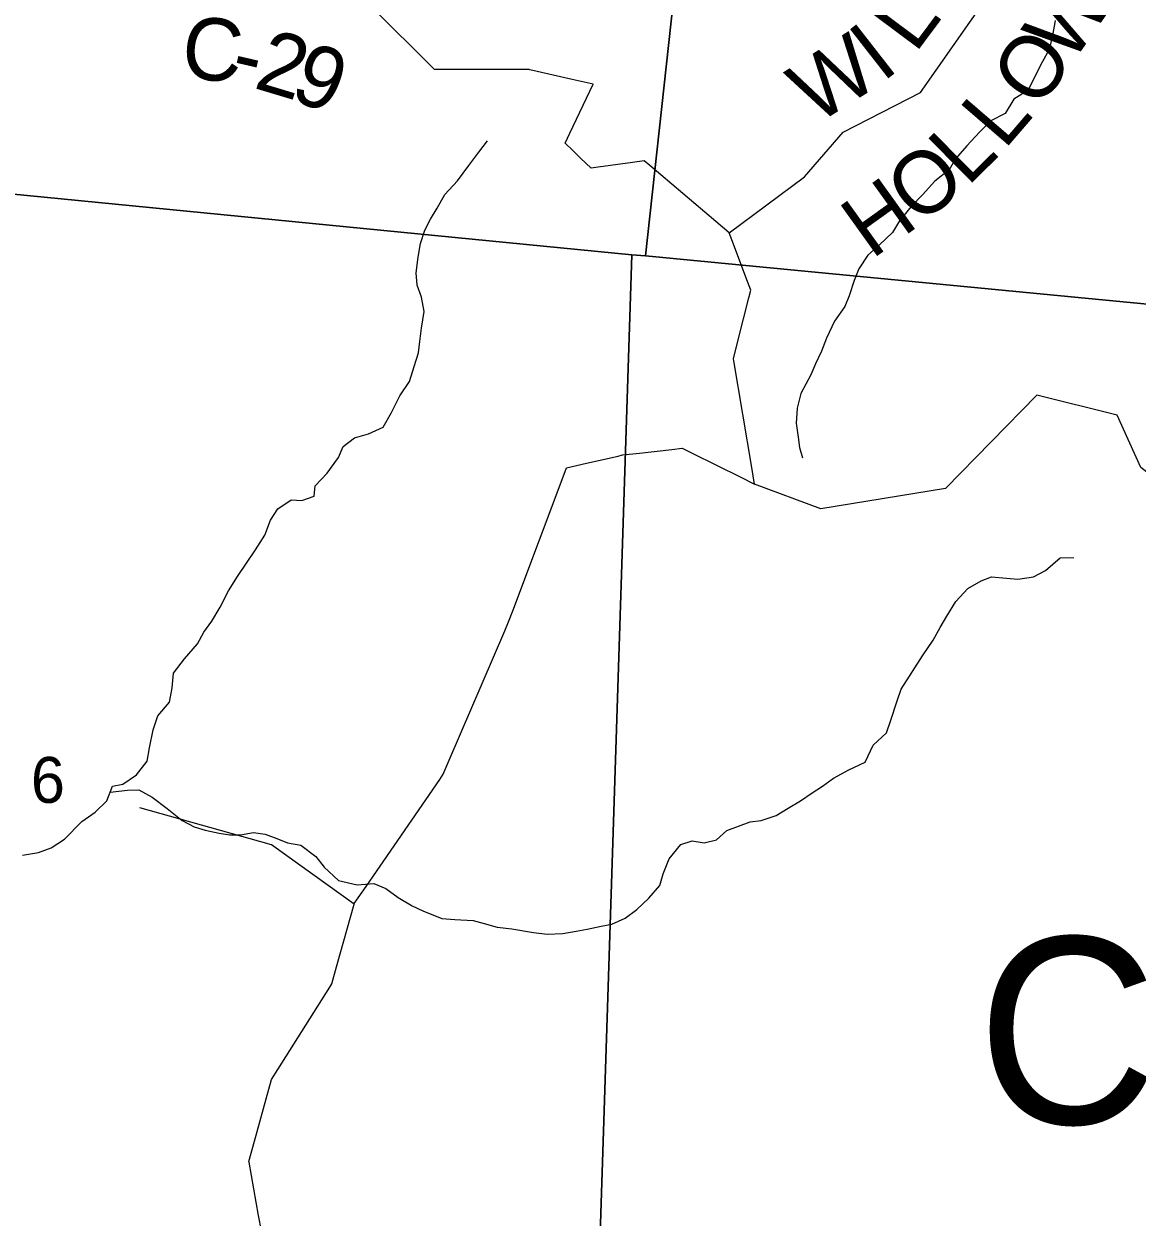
# Model space of a CAD drawing. Extents: x 1715311 to 2083412, y 146837 to 553079.
# Drawn here: x 1925685 to 1931050, y 401506 to 407256 of the extents above; entities that cross this region are included whole.
import ezdxf

# ---------------------------------------------------------------- set-up
doc = ezdxf.new("R2010")
doc.units = 0
for name, color, linetype in [('GM_X_County_Road', 7, 'Continuous'), ('GM_X_County_Road_Text', 7, 'Continuous'), ('GM_X_Minor_River', 7, 'Continuous'), ('GM_X_Section', 7, 'Continuous'), ('GM_X_Section_Text', 7, 'Continuous'), ('GM_X_Township_Road', 7, 'Continuous'), ('GM_X_Township_Road_Text', 7, 'Continuous'), ('GM_X_Township_ROW', 7, 'Continuous'), ('GM_X_Township_Text', 7, 'Continuous')]:
    doc.layers.add(name, color=color, linetype=linetype)

msp = doc.modelspace()

# ---------------------------------------------------------------- linework, layer by layer
at = {"layer": 'GM_X_County_Road'}
msp.add_lwpolyline([(1926830, 401440.6), (1926816.6, 401514.7), (1926770.3, 401771.3), (1926769.8, 401773.5), (1926796.8, 401871.9), (1926865.8, 402123.4), (1926878.1, 402168.6), (1926908.8, 402217.1), (1927159.2, 402614.2), (1927169, 402629.8), (1927192.1, 402712.4), (1927276.5, 403013.7), (1927277.3, 403016.8), (1927334.5, 403100), (1927689.4, 403615.5), (1927706.5, 403640.5), (1927735.6, 403708.4), (1928002.9, 404331.4), (1928021.4, 404374.5), (1928041.6, 404428.2), (1928298.5, 405111.6), (1928300.2, 405116.5), (1928396.7, 405138.7), (1928549.2, 405173.7), (1928571, 405178.7), (1928652.3, 405187.8), (1928807.8, 405205.2), (1928857.9, 405210.8), (1928906.2, 405186.9), (1929139.9, 405071.4), (1929206.8, 405038.3), (1929193.2, 405118.9), (1929106, 405633.1), (1929104.5, 405641.9), (1929128, 405734.3), (1929179.5, 405936.4), (1929188.8, 405972.8), (1929165.2, 406035.2), (1929110.1, 406181.6), (1929084.5, 406249.6), (1929020.5, 406303.8), (1928702.4, 406573.6), (1928675.3, 406596.6), (1928607.2, 406587), (1928452.3, 406565.2), (1928418.6, 406560.5), (1928368.1, 406609.3), (1928330.6, 406645.5), (1928294.2, 406680.8), (1928317.1, 406729.3), (1928428.4, 406965.1), (1928428.6, 406965.6), (1928327.5, 406988.6), (1928124.1, 407034.8), (1928119.7, 407035.8), (1927664.4, 407035.8), (1927620.7, 407079.1), (1927398.7, 407299.6)], dxfattribs=at)
at = {"layer": 'GM_X_Minor_River'}
for points in [[(1930654.7, 407272.8), (1930642.3, 407200.8), (1930625.8, 407132.8), (1930593.4, 407070.9), (1930557, 407003.1), (1930524.6, 406937.2), (1930456.4, 406893.6), (1930413.9, 406823.8), (1930345.8, 406788.2), (1930291.4, 406734.5), (1930229.1, 406668.9), (1930174.7, 406605.2), (1930144.4, 406553.3), (1930076.1, 406497.7), (1930015.7, 406432), (1929961.3, 406376.3), (1929904.9, 406306.6), (1929870.6, 406250.8), (1929808.2, 406191.1), (1929752, 406141.4), (1929709.5, 406075.6), (1929687.2, 406019.7), (1929662.7, 405945.8), (1929642.4, 405893.8), (1929592, 405824.1), (1929553.4, 405742.2), (1929529, 405678.3), (1929500.7, 405618.4), (1929478.3, 405564.5), (1929429.7, 405474.7), (1929411.3, 405404.8), (1929406.8, 405332.7), (1929416.3, 405264.5), (1929424, 405214.4), (1929437.6, 405164.3)], [(1925678.4, 403251), (1925756.4, 403262.5), (1925816.5, 403286.1), (1925880.8, 403327.7), (1925965.3, 403413.3), (1926029.5, 403456.9), (1926085.8, 403512.6), (1926112.2, 403582.5), (1926162.3, 403592.2), (1926228.5, 403637.8), (1926278.9, 403703.5), (1926291.3, 403767.5), (1926307.9, 403853.5), (1926330.3, 403921.5), (1926386.7, 403987.2), (1926399.2, 404057.2), (1926405.7, 404127.2), (1926460.1, 404197), (1926522.5, 404268.6), (1926552.9, 404324.5), (1926591.2, 404378.3), (1926631.6, 404446.1), (1926672.1, 404523.9), (1926714.5, 404593.8), (1926760.9, 404661.5), (1926801.3, 404721.3), (1926845.8, 404793.1), (1926874.2, 404865), (1926908.5, 404918.8), (1926972.8, 404962.5), (1927024.7, 404960.1), (1927084.8, 404979.8), (1927089.1, 405029.8), (1927147.5, 405091.5), (1927201.9, 405167.2), (1927224.3, 405219.1), (1927278.5, 405260.8), (1927346.6, 405280.4), (1927416.7, 405312), (1927457.2, 405383.8), (1927497.7, 405463.6), (1927544.1, 405533.4), (1927566.6, 405605.3), (1927587, 405671.3), (1927593.3, 405725.3), (1927601.8, 405789.3), (1927614.3, 405869.3), (1927600.8, 405939.5), (1927581.2, 405997.7), (1927575.6, 406055.8), (1927586.1, 406131.9), (1927596.6, 406197.9), (1927617, 406261.8), (1927645.3, 406315.7), (1927677.6, 406367.5), (1927714, 406433.4), (1927774.4, 406499.1), (1927828.9, 406572.8), (1927877.3, 406638.6), (1927919.6, 406692.3)], [(1926101.3, 403553.5), (1926184, 403564), (1926240, 403565.6), (1926303.7, 403529.1), (1926375.2, 403474.6), (1926448.8, 403418), (1926506.5, 403387.6), (1926558.4, 403371.2), (1926626.2, 403356.8), (1926678.1, 403348.4), (1926730, 403348.1), (1926792, 403359.7), (1926847.9, 403351.3), (1926903.7, 403330.9), (1926955.5, 403310.5), (1927019.4, 403298.1), (1927092.9, 403243.5), (1927132.5, 403193.2), (1927202, 403128.6), (1927291.8, 403108), (1927371.8, 403113.5), (1927429.5, 403089.1), (1927489.2, 403046.6), (1927556.8, 403006.1), (1927608.6, 402981.7), (1927700.3, 402945.1), (1927762.2, 402940.7), (1927850.1, 402936.1), (1927903.9, 402921.7), (1927965.7, 402903.2), (1928037.6, 402894.8), (1928141.4, 402878), (1928207.2, 402869.6), (1928283.2, 402873.1), (1928347.2, 402884.7), (1928399.2, 402894.3), (1928467.2, 402907.9), (1928519.2, 402917.6), (1928583.4, 402947.2), (1928639.6, 402988.9), (1928697.9, 403042.5), (1928750.3, 403104.3), (1928766.6, 403160.2), (1928795.1, 403232.1), (1928851.5, 403301.8), (1928905.6, 403319.5), (1928963.5, 403309.1), (1929023.5, 403324.7), (1929073.7, 403368.4), (1929185.9, 403411.7), (1929237.9, 403417.4), (1929310, 403441), (1929368.2, 403476.6), (1929428.4, 403512.2), (1929484.6, 403549.9), (1929534.7, 403583.6), (1929586.9, 403621.3), (1929661.1, 403660.9), (1929739.3, 403698.4), (1929777.8, 403780.2), (1929842.2, 403839.9), (1929862.5, 403895.8), (1929893.2, 403993.8), (1929913.5, 404049.7), (1929968.1, 404135.4), (1930016.5, 404211.2), (1930067, 404287), (1930101.4, 404346.8), (1930133.7, 404402.6), (1930176.1, 404472.5), (1930234.5, 404536.1), (1930298.7, 404571.8), (1930348.8, 404591.5), (1930420.7, 404585), (1930474.6, 404580.6), (1930550.6, 404592.1), (1930608.7, 404621.8), (1930679.1, 404683.4), (1930745, 404684.9)]]:
    msp.add_lwpolyline(points, dxfattribs=at)
at = {"layer": 'GM_X_Section'}
for points in [[(1923755.4, 411934.6), (1929216.1, 411031.3), (1928680.9, 406138.8), (1928614.9, 406143), (1923293.4, 406665.7)], [(1929216.1, 411031.3), (1935235.3, 410505), (1934851, 405539.9), (1934537, 405574.1), (1928680.9, 406138.8)], [(1923293.4, 406665.7), (1928614.9, 406143), (1928437.8, 400678.8), (1922848.3, 401226.1)], [(1928614.9, 406143), (1928680.9, 406138.8), (1934537, 405574.1), (1934039.3, 400155.9), (1928437.8, 400678.8)]]:
    msp.add_lwpolyline(points, close=True, dxfattribs=at)
at = {"layer": 'GM_X_Township_Road'}
for points in [[(1929084.5, 406249.6), (1929446.8, 406518.7), (1929633.6, 406735), (1930005.6, 406925.2), (1930794.3, 408050.7), (1930933.4, 408344.8), (1930962.3, 408834.4), (1930805.4, 409446.3)], [(1934122.1, 405171.2), (1933393, 405289.9), (1933013, 405146.7), (1932735.5, 404694.2), (1932169.2, 404496.7), (1931712.2, 404695.8), (1931485.7, 404701.1), (1931176.2, 405034.6), (1931068.5, 405118.8), (1930953.3, 405371.2), (1930566.7, 405467.5), (1930126.6, 405017.7), (1929526, 404919), (1929206.8, 405038.3)]]:
    msp.add_lwpolyline(points, dxfattribs=at)
at = {"layer": 'GM_X_Township_ROW'}
msp.add_lwpolyline([(1927276.5, 403013.7), (1926878.9, 403300.1), (1926244.3, 403478.1)], dxfattribs=at)

# ---------------------------------------------------------------- texts
at = {"layer": 'GM_X_County_Road_Text'}
for s, rotation, p in [('C', 354.12358, (1926436.2, 406999.4)), ('2', 343.28331, (1926786.6, 406949.2)), ('9', 338.79773, (1926957.8, 406898.1)), ('-', 346.92933, (1926671.5, 406975.8))]:
    msp.add_text(s, height=300, rotation=rotation, dxfattribs=at).set_placement(p)
at = {"layer": 'GM_X_Section_Text'}
msp.add_text('6', height=221, rotation=0.00001, dxfattribs=at).set_placement((1925719, 403502.5))
at = {"layer": 'GM_X_Township_Road_Text'}
for s, rotation, p in [('W', 55.0403, (1930731.4, 407055.1)), ('L', 53.28397, (1929980.5, 407109)), ('W', 32.17899, (1929501, 406766.7)), ('I', 37.95063, (1929822.2, 406970.8)), ('O', 54.06543, (1930573.2, 406836.8)), ('L', 49.29365, (1930409.9, 406645.3)), ('L', 44.65122, (1930232.2, 406468.2)), ('O', 38.10063, (1929996.4, 406280.6)), ('H', 35.65455, (1929770.7, 406118.3))]:
    msp.add_text(s, height=300, rotation=rotation, dxfattribs=at).set_placement(p)
at = {"layer": 'GM_X_Township_Text'}
msp.add_text('COAL', height=900, rotation=0.00001, dxfattribs=at).set_placement((1930279, 401955.4))

doc.saveas('drawing.dxf')
